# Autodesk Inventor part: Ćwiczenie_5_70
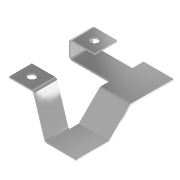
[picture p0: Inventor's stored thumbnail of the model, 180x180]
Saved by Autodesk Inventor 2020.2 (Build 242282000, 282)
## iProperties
Created: 2006-10
Part Number: Ćwiczenie_5_70
Document SubType Name: Konstrukcje blachowe
Designer: F.Stasiak
Density: 1 g/cm^3
Sheet Metal Rule: Domyślnie
Material: Ogólny
Appearance: Chrom — polerowany
Manager: www.cadconsulting.pl
Company: Fabian Stasiak CAD Consulting
Author: F.Stasiak
Subject: Zbiór ćwiczeń. Autodesk Inventor 2020. Kurs podstawowy
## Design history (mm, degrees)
node "Powierzchnia1"
  sketch "Szkic1"
    geometry: L1 (0, 60)-(-40, 60); L2 (-40, 60)-(-40, 0); L3 (-40, 0)-(0, 0); L4 (0, 0)-(0, 60); 1 further point
    constraints: 8 end point, 2 parallel, 1 coincident, 1 horizontal, 1 perpendicular
    dimensions: "d0" = 40 distance of L2.end L3.end; "d1" = 60 distance of L3.end L1.start
node "Kołnierz1"
node "Kołnierz2"
node "Płaszczyzna konstrukcyjna1"
node "Powierzchnia2"
  sketch "Szkic4"
    geometry: L1 (-50.124, -15)-(-20.124, -15); L2 (-20.124, -15)-(-20.124, -45); L3 (-20.124, -45)-(-50.124, -45); L4 (-50.124, -45)-(-50.124, -15); L5 (-50.124, -98.284)-(-20.124, -98.284); L6 (-20.124, -98.284)-(-20.124, -128.284); L7 (-20.124, -128.284)-(-50.124, -128.284); L8 (-50.124, -128.284)-(-50.124, -98.284); L9 (0, 0)-(40, 0) reference; L10 (40, -128.284)-(0, -128.284) reference
    constraints: 16 end point, 4 parallel, 2 equal length, 2 horizontal, 2 perpendicular, 1 collinear
    dimensions: "d18" = 30 distance of L3.end L1.start; "d19" = 30 distance of L1.start L1.end; "d20" = 15 distance between parallel lines of L9 L1; "d21" = 0 distance between parallel lines of L10 L7
feature "Gięcie4" dims "d27" = 2 (= SzerokośćGięciaPodcięcia), "d28" = 1 (= GłębokośćGięciaPodcięcia), "d29" = 4 (= MinimalnaPozostałość), "d30" = 2 (= PromieńGięcia), "d31" = 2 (= PromieńGięcia), "d44" = 2 (= Grubość), "OdstępPołączenia" = 0.01
feature "Gięcie5" dims "d32" = 2 (= SzerokośćGięciaPodcięcia), "d33" = 1 (= GłębokośćGięciaPodcięcia), "d34" = 4 (= MinimalnaPozostałość), "d35" = 2 (= PromieńGięcia), "d36" = 2 (= PromieńGięcia), "d44" = 2 (= Grubość), "OdstępPołączenia" = 0.01
sketch "Szkic5"
  geometry: L1 (-30, 30)-(0, 30) reference; L2 (-30, 0)-(-30, 30) reference; L3 (0, 0)-(-30, 0) reference; L4 (0, 30)-(0, 0) reference; L5 (0, -53.284)-(0, -83.284) reference; L6 (-30, -53.284)-(0, -53.284) reference; L7 (-30, -83.284)-(-30, -53.284) reference; L8 (0, -83.284)-(-30, -83.284) reference; L9 (-15, -83.284)-(-15, -53.284); L10 (-15, 0)-(-15, 30); 2 further points
  constraints: 6 midpoint, 4 end point
hole "Otwór1" sketch "Szkic5" at (-15, -68.284), (-15, 15) diameter "d37" = 10; stored, may be unused: countersink angle "d41" = 90 deg, drill point angle "d43" = 118 deg; dims "d38" = 6, "d39" = 4, "d40" = 2, "d42" = 2 (= Grubość)
node "Bryła1"
node "Korpusy bryłowe"
node "Korpusy powierzchniowe"
feature "Płyta1" dims "d44" = 2 (= Grubość)
sketch "Szkic2"
  geometry: L1 (40, 0)-(40, 40); L2 (40, 40)-(0, 40); 1 other entity
  constraints: 4 end point, 4 other
feature "Płyta2" dims "d3" = 2 (= SzerokośćGięciaPodcięcia), "d5" = 4 (= MinimalnaPozostałość), "d7" = 40, "d8" = 45 deg, "d9" = 2 (= PromieńGięcia), "d44" = 2 (= Grubość)
feature "Gięcie1" dims "d3" = 2 (= SzerokośćGięciaPodcięcia), "d4" = 1 (= GłębokośćGięciaPodcięcia), "d5" = 4 (= MinimalnaPozostałość), "d6" = 2 (= PromieńGięcia), "d7" = 40, "d8" = 45 deg, "d9" = 2 (= PromieńGięcia), "d44" = 2 (= Grubość), "OdstępPołączenia" = 0.01
sketch "Szkic3"
  geometry: L1 (40, 0)-(40, 40); L2 (40, 40)-(0, 40); 1 other entity
  constraints: 4 end point, 4 other
feature "Płyta3" dims "d10" = 2 (= SzerokośćGięciaPodcięcia), "d12" = 4 (= MinimalnaPozostałość), "d14" = 40, "d15" = 45 deg, "d16" = 2 (= PromieńGięcia), "d44" = 2 (= Grubość)
feature "Gięcie2" dims "d10" = 2 (= SzerokośćGięciaPodcięcia), "d11" = 1 (= GłębokośćGięciaPodcięcia), "d12" = 4 (= MinimalnaPozostałość), "d13" = 2 (= PromieńGięcia), "d14" = 40, "d15" = 45 deg, "d16" = 2 (= PromieńGięcia), "d44" = 2 (= Grubość), "OdstępPołączenia" = 0.01
feature "Płyta4" dims "d22" = 2 (= PromieńGięcia), "d23" = 2 (= SzerokośćGięciaPodcięcia), "d25" = 4 (= MinimalnaPozostałość), "d44" = 2 (= Grubość)
feature "Gięcie3" dims "d22" = 2 (= PromieńGięcia), "d23" = 2 (= SzerokośćGięciaPodcięcia), "d24" = 1 (= GłębokośćGięciaPodcięcia), "d25" = 4 (= MinimalnaPozostałość), "d26" = 2 (= PromieńGięcia), "d44" = 2 (= Grubość), "OdstępPołączenia" = 0.01
node "Pętla rzutowana1"
node "Pętla rzutowana2"
other parameters: "Grubość" = 2, "PromieńGięcia" = 2 (= Grubość), "SzerokośćGięciaPodcięcia" = 2 (= Grubość), "GłębokośćGięciaPodcięcia" = 1 (= 0.5 x Grubość), "RozmiarPodcięciaNarożnika" = 8 (= 4 x Grubość), "MinimalnaPozostałość" = 4 (= 2 x Grubość), "PromieńPrzejścia" = 2 (= PromieńGięcia), "d2" = 2 (= PromieńGięcia), "Rozmiar_promienia_Jacobiego" = 2 (= Grubość), "Wielk_odstępu" = 2 (= Grubość)
